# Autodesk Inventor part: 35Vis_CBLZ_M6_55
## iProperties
Created: 2011-01
Part Number: 35Vis_CBLZ_M6_55
Document SubType Name: Modeling
Designer: eric
Density: 1 g/cm^3
Mass: 1.76846 g
Surface Area: 13.588 cm^2
Volume: 1.76846 cm^3
Author: eric
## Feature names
1. Base1
